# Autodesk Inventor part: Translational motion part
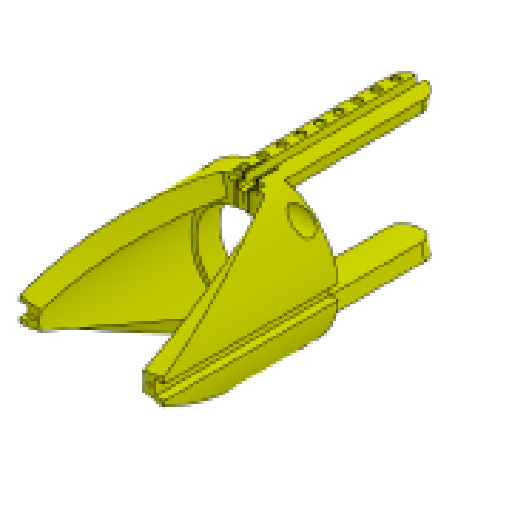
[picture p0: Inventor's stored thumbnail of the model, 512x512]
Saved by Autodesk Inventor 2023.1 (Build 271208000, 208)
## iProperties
Created: 2020-02
Part Number: Translational motion part
Material: Generic
Document SubType Name: Modeling
Designer: ftrauzettel
Density: 1 g/cm^3
Appearance: Generic
Sending System: SolidWorks 2016
Last Author: Pam
Last Saved: 2020-06-08
Author: ftrauzettel
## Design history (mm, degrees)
feature "CirPattern5"
sketch "Sketch2"
  geometry: L1 (-2.5, 46.5)-(-2.2, 46.5); L2 (-2.2, 46.5)-(-2.2, -3.5); L3 (-2.2, -3.5)-(-2.5, -3.5); L4 (-2.5, -3.5)-(-2.5, 46.5); L5 (2.2, 46.5)-(2.5, 46.5); L6 (2.5, 46.5)-(2.5, -3.5); L7 (2.5, -3.5)-(2.2, -3.5); L8 (2.2, -3.5)-(2.2, 46.5); A1 r 25 centre (0, 21.5) between (-1.55, 46.452) and (-5, 45.995) reference; A2 r 25 centre (0, 21.5) between (-5, -2.995) and (-1.55, -3.452) reference; A3 r 25 centre (0, 21.5) between (1.55, -3.452) and (5, -2.995) reference
  constraints: 16 end point, 4 parallel, 3 tangent, 2 horizontal, 2 perpendicular, 1 horizontal alignment
  dimensions: "d30" = 0.3 distance of L2.end L3.end; "d31" = 0.3 distance of L6.end L7.end; "d32" = 4.4 distance between parallel lines of L8 L2; "d33" = 2.2 distance from line of A1.centre L2 (= 0.5 x d32)
extrude "Extrusion1" cut sketch "Sketch2" distance "d6" = 10; taper "d7" = 0 deg
sketch "Sketch4"
  geometry: L1 (15.811, 8)-(19.068, 8) reference; L2 (15.811, 0)-(15.811, 8) reference; L3 (19.849, 0)-(15.811, 0) reference; L4 (19.849, -2)-(19.849, 0) reference; L5 (24.88, -2)-(19.849, -2) reference; L6 (24.88, 8)-(24.88, -2) reference; L7 (24.068, 8)-(24.88, 8) reference; L8 (24.068, 71.5)-(24.068, 8) reference; L9 (19.068, 71.5)-(24.068, 71.5) reference; L10 (19.068, 8)-(19.068, 71.5) reference; L11 (21.5, -52.912)-(21.5, 8) reference; 2 further points
  dimensions: "d8" = 4 distance from line of L3 point (18.656, 4) (= 0.5 x d9); "d9" = 8 distance of L2.start L1.start (derived); "d11" = 5.68872 distance between parallel lines of L2 L11 (derived); "d12" = 2.84436 distance from line of L2 point (18.656, 4) (= 0.5 x d11)
  node "Reference5"
workplane "Work Plane1"
sketch "Sketch5"
  geometry: 1 further point
hole "Hole1" sketch "Sketch5" at (18.656, -56) diameter "d13" = 3.4; stored, may be unused: countersink angle "d17" = 90 deg, drill point angle "d19" = 118 deg; dims "d14" = 6, "d15" = 6.5, "d16" = 17.6875, "d18" = 8
hole "Hole2" sketch "Sketch4" diameter "d20" = 2.459; stored, may be unused: countersink angle "d24" = 90 deg, drill point angle "d26" = 118 deg; dims "d21" = 6, "d22" = 6.5, "d23" = 17.6875, "d25" = 8
pattern_circular "Circular Pattern1" dims angle "d28" = 360 deg
body "Solid1"
